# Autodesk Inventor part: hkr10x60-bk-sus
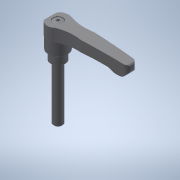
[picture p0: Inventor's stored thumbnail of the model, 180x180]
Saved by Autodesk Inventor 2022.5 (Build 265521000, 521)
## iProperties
Created: 2017-09
Part Number: hkr10x60-bk-sus
Material: 一般
Document SubType Name: Modeling
Designer: imaocorp
Density: 1 g/cm^3
Appearance: 既定
Author: imaocorp
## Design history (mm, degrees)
node "hkr10x60-bk-sus.x_t1"
node "hkr10x60-bk-sus"
node "Base1"
